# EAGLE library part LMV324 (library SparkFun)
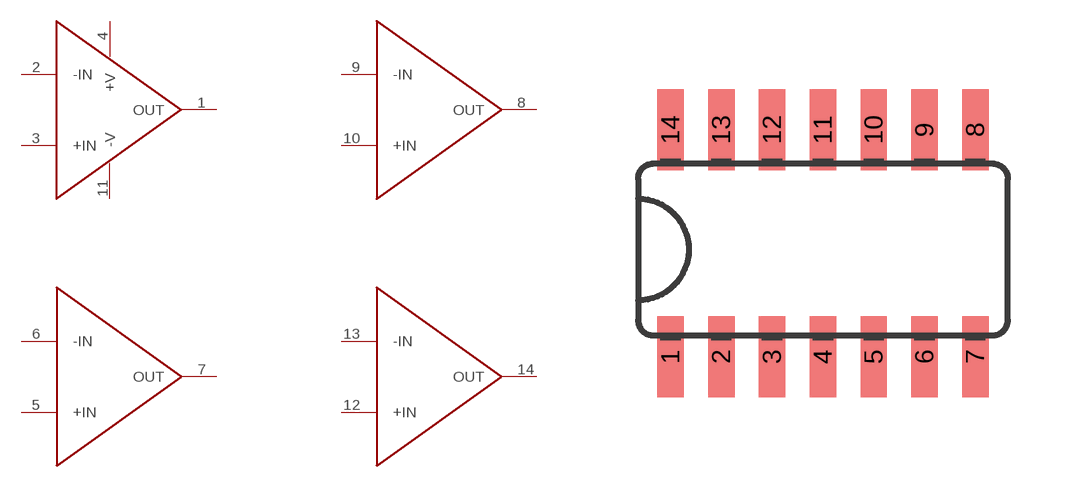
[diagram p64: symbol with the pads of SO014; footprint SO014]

Designator prefix -; gates G$1=LMV324 G$2=LMV324_2 G$3=LMV324_2 G$4=LMV324_2

## LMV324  [SO014]
1  G$1:OUT  out
2  G$1:-IN  in
3  G$1:+IN  in
4  G$1:+V  pwr
5  G$2:+IN  pwr
6  G$2:-IN  pwr
7  G$2:OUT  pwr
8  G$3:OUT  pwr
9  G$3:-IN  pwr
10  G$3:+IN  pwr
11  G$1:-V  pwr
12  G$4:+IN  pwr
13  G$4:-IN  pwr
14  G$4:OUT  pwr

## Footprint SO014 (pad centres in mm)
smd 0.66 x 2.032: 1 -3.175,-2.68; 2 -1.905,-2.68; 3 -0.635,-2.68; 4 0.635,-2.68; 5 1.905,-2.68; 6 3.175,-2.68; 7 4.445,-2.68; 8 4.445,2.997; 9 3.175,2.997; 10 1.905,2.997; 11 0.635,2.997; 12 -0.635,2.997; 13 -1.905,2.997; 14 -3.175,2.997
